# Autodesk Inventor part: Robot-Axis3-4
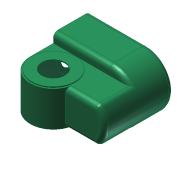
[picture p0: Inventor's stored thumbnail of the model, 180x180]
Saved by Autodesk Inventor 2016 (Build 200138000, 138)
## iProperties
Shininess: 21.0
Length Units: 11269
Angle Units: 11279
Time Units: 11290
Mass Units: 11283
Length Display Precision: 3
Angle Display Precision: 2
Created: 2001-08
Part Number: Robot-Axis3-4
Document SubType Name: ﾓﾃﾞﾘﾝｸﾞ
Designer: Administrator
Density: 1 g/cm^3
Material: Generic
Mass: 220.721 g
Surface Area: 2216.89 cm^2
Volume: 220.721 cm^3
Appearance: Sea Green
Density: 0.0
Volumn: 0.0
Area: 0.0
PropertySet Name: Model Information
Control State: 0
Master: False
Checked Out: False
Author: Administrator
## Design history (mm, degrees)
sketch "ｽｹｯﾁ1"
  geometry: L1 (-50, 0)-(-50, 68.315); L2 (130, 50)-(-50, 50); L3 (50, 0)-(50, 50); L4 (130, 50)-(130, -20); L5 (45.826, -20)-(130, -20); A1 r 50 centre (0, 0) between (-50, 0) and (50, 0); 1 further point
  constraints: 10 end point, 3 perpendicular, 3 point on circle, 3 tangent, 2 point on line, 1 centre point, 1 coincident, 1 parallel, 1 vertical, 1 other
  dimensions: "d0" = 100 diameter of A1; "d10" = 20 distance from line of L5 A1.centre; "d11" = 180 distance between parallel lines of L4 L1
extrude "押し出し1" new body sketch "ｽｹｯﾁ1" stored distance "d1" = 76; taper "d2" = 0 deg
sketch "ｽｹｯﾁ2"
  geometry: C1 r 50 at (0, 0) reference; C2 r 47 at (0, 0)
  constraints: 1 centre point
  dimensions: "d3" = 3 radial gap between concentric circles of C1 C2
extrude "押し出し2" join sketch "ｽｹｯﾁ2" distance "d4" = 2; taper "d5" = 0 deg
sketch "ｽｹｯﾁ3"
  geometry: L1 (-50, 50)-(-50, 130); L2 (-50, 130)-(130, 130); L3 (-53.41, 90)-(-7.321, 90); L4 (130, 50)-(-50, 50) reference; L5 (-50, 50)-(130, 50); L6 (130, 50)-(130, 130); C1 r 50 at (0, 0) reference
  constraints: 10 end point, 1 collinear, 1 parallel, 1 perpendicular, 1 tangent, 1 vertical
  dimensions: "d6" = 90 distance from line of L3 C1.centre; "d7" = 40 distance between parallel lines of L3 L2; "d8" = 180 distance of L1.end L2.end
extrude "押し出し3" join sketch "ｽｹｯﾁ3" stored distance "d12" = 116; taper "d13" = 0 deg
sketch "ｽｹｯﾁ4"
  geometry: L1 (-20, 130)-(96, 130) reference; L2 (0, 0)-(76, 0) reference; L3 (-37.109, 90)-(114.915, 90); L4 (38, 130)-(38, 36.926); C1 r 37 at (38, 90)
  constraints: 4 end point, 2 point on line, 1 centre point, 1 midpoint, 1 parallel, 1 perpendicular
  dimensions: "d14" = 90 distance between parallel lines of L3 L2; "d15" = 74 diameter of C1
extrude "押し出し4" join sketch "ｽｹｯﾁ4" distance "d16" = 1; taper "d17" = 0 deg
fillet "Chamfer1" dims "d18" = 58
fillet "Chamfer2" dims "d19" = 10
fillet "Chamfer3" dims "d20" = 10
shell "Shell1" dims "d28" = 2
sketch "Sketch5"
  geometry: C1 r 47 at (0, 0) reference
hole "Hole1" sketch "Sketch5" at (0, 0) diameter "d21" = 50; stored, may be unused: countersink angle "d25" = 82 deg, drill point angle "d27" = 118 deg; dims "d22" = 6, "d23" = 4, "d24" = 2, "d26" = 2
sketch "Sketch6"
  geometry: C1 r 37 at (0, 0) reference
hole "Hole2" sketch "Sketch6" at (0, 0) diameter "d29" = 50; stored, may be unused: countersink angle "d33" = 82 deg, drill point angle "d35" = 118 deg; dims "d30" = 6, "d31" = 4, "d32" = 2, "d34" = 2
body "Solid1"
mirror "Mirror1"
